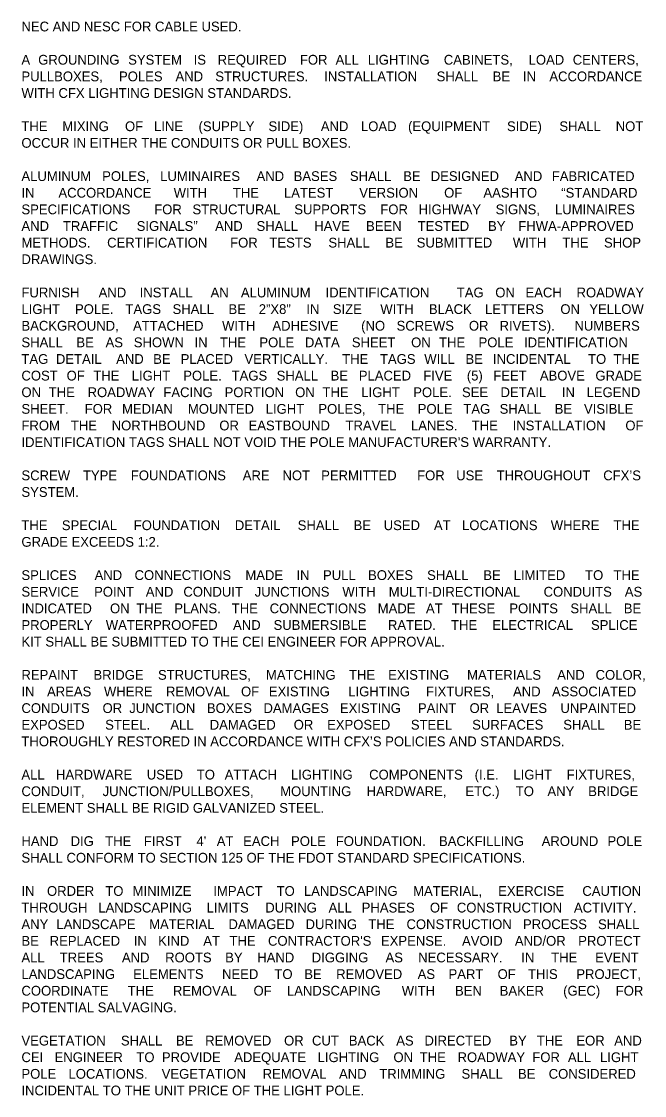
# Model space of a CAD drawing. Extents: x -55 to 2471539, y -90 to 3608906.
# Drawn here: x 568 to 1014, y 8 to 777 of the extents above; entities that cross this region are included whole.
import ezdxf

# ---------------------------------------------------------------- set-up
doc = ezdxf.new("R2010")
doc.units = 0
doc.layers.add('XSCell', color=7, linetype='Continuous')

msp = doc.modelspace()

# ---------------------------------------------------------------- texts
at = {"layer": 'XSCell'}
for s, p in [('NEC AND NESC FOR CABLE USED.', (568.01, 770.14)), ('GROUNDING ', (580.01, 746.34)), ('SYSTEM ', (644.47, 746.34)), ('IS ', (691.38, 746.34)), ('REQUIRED ', (708.58, 746.34)), ('FOR ', (767.49, 746.34)), ('LIGHTING ', (816.15, 746.34)), ('CABINETS, ', (870.55, 746.34)), ('LOAD ', (931.31, 746.34)), ('CENTERS, ', (962.92, 746.34)), ('A ', (568.01, 746.34)), ('ALL ', (793.05, 746.34)), ('PULLBOXES, ', (568.01, 734.44)), ('POLES ', (637.9, 734.44)), ('AND ', (678.37, 734.44)), ('STRUCTURES. ', (706.88, 734.44)), ('INSTALLATION ', (784.88, 734.44)), ('SHALL ', (865.42, 734.44)), ('BE ', (905.55, 734.44)), ('IN ', (927.24, 734.44)), ('ACCORDANCE ', (946.18, 734.44)), ('WITH CFX LIGHTING DESIGN STANDARDS.', (568.01, 722.54)), ('THE ', (568.01, 698.74)), ('MIXING ', (597.31, 698.74)), ('OF ', (642.19, 698.74)), ('LINE ', (663, 698.74)), ('(SUPPLY ', (694.88, 698.74)), ('SIDE) ', (744.95, 698.74)), ('AND ', (782.46, 698.74)), ('LOAD ', (811.22, 698.74)), ('(EQUIPMENT ', (844.96, 698.74)), ('SIDE) ', (915.82, 698.74)), ('SHALL ', (953.33, 698.74)), ('NOT ', (993.71, 698.74)), ('OCCUR IN EITHER THE CONDUITS OR PULL BOXES.', (568.01, 686.84)), ('ALUMINUM ', (568.01, 663.04)), ('POLES, ', (625.83, 663.04)), ('LUMINAIRES ', (667.41, 663.04)), ('AND ', (736.42, 663.04)), ('BASES ', (762.98, 663.04)), ('SHALL ', (803.29, 663.04)), ('BE ', (841.48, 663.04)), ('DESIGNED ', (861.21, 663.04)), ('AND ', (921.34, 663.04)), ('FABRICATED ', (947.9, 663.04)), ('IN ', (568.01, 651.14)), ('ACCORDANCE ', (594.51, 651.14)), ('WITH ', (677.06, 651.14)), ('THE ', (719.43, 651.14)), ('LATEST ', (756.05, 651.14)), ('VERSION ', (810.01, 651.14)), ('OF ', (870.8, 651.14)), ('AASHTO ', (898.93, 651.14)), ('“STANDARD ', (954.69, 651.14)), ('SPECIFICATIONS ', (568.01, 639.24)), ('FOR ', (663.12, 639.24)), ('STRUCTURAL ', (690.51, 639.24)), ('SUPPORTS ', (763.45, 639.24)), ('FOR ', (825.09, 639.24)), ('HIGHWAY ', (852.48, 639.24)), ('SIGNS, ', (907.69, 639.24)), ('LUMINAIRES ', (950.21, 639.24)), ('AND ', (568.01, 627.34)), ('TRAFFIC ', (597.7, 627.34)), ('SIGNALS” ', (650.56, 627.34)), ('AND ', (706.75, 627.34)), ('SHALL ', (736.44, 627.34)), ('HAVE ', (777.76, 627.34)), ('BEEN ', (814.87, 627.34)), ('TESTED ', (851.81, 627.34)), ('BY ', (902.26, 627.34)), ('FHWA-APPROVED ', (923.92, 627.34)), ('METHODS. ', (568.01, 615.44)), ('CERTIFICATION ', (629.39, 615.44)), ('FOR ', (717.5, 615.44)), ('TESTS ', (745.65, 615.44)), ('SHALL ', (787.89, 615.44)), ('BE ', (828.73, 615.44)), ('SUBMITTED ', (851.14, 615.44)), ('WITH ', (920.02, 615.44)), ('THE ', (955.54, 615.44)), ('SHOP ', (985.31, 615.44)), ('DRAWINGS.', (568.01, 603.54)), ('FURNISH ', (568.01, 579.74)), ('AND ', (623.29, 579.74)), ('INSTALL ', (652.69, 579.74)), ('AN ', (703.49, 579.74)), ('ALUMINUM ', (725.21, 579.74)), ('IDENTIFICATION ', (785.87, 579.74)), ('TAG ', (879.86, 579.74)), ('ON ', (907.43, 579.74)), ('EACH ', (929.1, 579.74)), ('ROADWAY ', (965.64, 579.74)), ('LIGHT ', (568.01, 567.84)), ('POLE. ', (606.39, 567.84)), ('TAGS ', (642.51, 567.84)), ('SHALL ', (676.24, 567.84)), ('BE ', (716.34, 567.84)), ('2”X8” ', (738.01, 567.84)), ('IN ', (772.11, 567.84)), ('SIZE ', (791.03, 567.84)), ('WITH ', (825.09, 567.84)), ('BLACK ', (859.87, 567.84)), ('LETTERS ', (900.07, 567.84)), ('ON ', (954.05, 567.84)), ('YELLOW ', (974.8, 567.84)), ('BACKGROUND, ', (568.01, 555.94)), ('ATTACHED ', (647.98, 555.94)), ('WITH ', (711.72, 555.94)), ('ADHESIVE ', (747.77, 555.94)), ('(NO ', (811.36, 555.94)), ('SCREWS ', (836.74, 555.94)), ('OR ', (888.54, 555.94)), ('RIVETS). ', (910.5, 555.94)), ('NUMBERS ', (964.15, 555.94)), ('SHALL ', (568.01, 544.04)), ('BE ', (607.37, 544.04)), ('AS ', (628.28, 544.04)), ('SHOWN ', (648.48, 544.04)), ('IN ', (691.99, 544.04)), ('THE ', (710.16, 544.04)), ('POLE ', (738.44, 544.04)), ('DATA ', (771.06, 544.04)), ('SHEET ', (804.66, 544.04)), ('ON ', (847.15, 544.04)), ('THE ', (867.16, 544.04)), ('POLE ', (895.44, 544.04)), ('IDENTIFICATION ', (928.06, 544.04)), ('TAG ', (568.01, 532.14)), ('DETAIL ', (592.69, 532.14)), ('AND ', (635.86, 532.14)), ('BE ', (662.38, 532.14)), ('PLACED ', (682.08, 532.14)), ('VERTICALLY. ', (727.77, 532.14)), ('THE ', (797.76, 532.14)), ('TAGS ', (824.83, 532.14)), ('WILL ', (856.59, 532.14)), ('BE ', (886.05, 532.14)), ('INCIDENTAL ', (905.75, 532.14)), ('TO ', (973.89, 532.14)), ('THE ', (992.12, 532.14)), ('COST ', (568.01, 520.24)), ('OF ', (600.37, 520.24)), ('THE ', (619.44, 520.24)), ('LIGHT ', (647, 520.24)), ('POLE. ', (683.91, 520.24)), ('TAGS ', (718.57, 520.24)), ('SHALL ', (750.83, 520.24)), ('BE ', (789.47, 520.24)), ('PLACED ', (809.66, 520.24)), ('FIVE ', (855.85, 520.24)), ('(5) ', (887.05, 520.24)), ('FEET ', (906.02, 520.24)), ('ABOVE ', (939.36, 520.24)), ('GRADE ', (979.17, 520.24)), ('ON ', (568.01, 508.34)), ('THE ', (587.57, 508.34)), ('ROADWAY ', (615.39, 508.34)), ('FACING ', (669.69, 508.34)), ('PORTION ', (713.51, 508.34)), ('ON ', (764.09, 508.34)), ('THE ', (783.65, 508.34)), ('LIGHT ', (811.48, 508.34)), ('POLE. ', (848.66, 508.34)), ('SEE ', (883.58, 508.34)), ('DETAIL ', (911.18, 508.34)), ('IN ', (955.12, 508.34)), ('LEGEND ', (972.84, 508.34)), ('SHEET. ', (568.01, 496.44)), ('FOR ', (613.33, 496.44)), ('MEDIAN ', (640.07, 496.44)), ('MOUNTED ', (687.27, 496.44)), ('LIGHT ', (742.99, 496.44)), ('POLES, ', (780.69, 496.44)), ('THE ', (823.52, 496.44)), ('POLE ', (851.88, 496.44)), ('TAG ', (884.57, 496.44)), ('SHALL ', (910.54, 496.44)), ('BE ', (949.98, 496.44)), ('VISIBLE ', (970.96, 496.44)), ('FROM ', (568.01, 484.54)), ('THE ', (603.39, 484.54)), ('NORTHBOUND ', (632.65, 484.54)), ('OR ', (709.75, 484.54)), ('EASTBOUND ', (730.69, 484.54)), ('TRAVEL ', (800.16, 484.54)), ('LANES. ', (847.03, 484.54)), ('THE ', (890.59, 484.54)), ('INSTALLATION ', (919.86, 484.54)), ('OF ', (1000.61, 484.54)), ("IDENTIFICATION TAGS SHALL NOT VOID THE POLE MANUFACTURER'S WARRANTY.", (568.01, 472.64)), ('SCREW ', (568.01, 448.84)), ('TYPE ', (612.05, 448.84)), ('FOUNDATIONS ', (646.38, 448.84)), ('ARE ', (726.54, 448.84)), ('NOT ', (755, 448.84)), ('PERMITTED ', (782.71, 448.84)), ('FOR ', (851.45, 448.84)), ('USE ', (879.44, 448.84)), ('THROUGHOUT ', (908.4, 448.84)), ('CFX’S ', (984.76, 448.84)), ('SYSTEM.', (568.01, 436.94)), ('THE ', (568.01, 413.14)), ('SPECIAL ', (596.95, 413.14)), ('FOUNDATION ', (648.45, 413.14)), ('DETAIL ', (720.86, 413.14)), ('SHALL ', (765.91, 413.14)), ('BE ', (805.93, 413.14)), ('USED ', (827.51, 413.14)), ('AT ', (863.48, 413.14)), ('LOCATIONS ', (883.63, 413.14)), ('WHERE ', (947.18, 413.14)), ('THE ', (992.12, 413.14)), ('GRADE EXCEEDS 1:2.', (568.01, 401.24)), ('SPLICES ', (568.01, 377.44)), ('AND ', (620.4, 377.44)), ('CONNECTIONS ', (649.03, 377.44)), ('MADE ', (728.42, 377.44)), ('IN ', (764.98, 377.44)), ('PULL ', (784.04, 377.44)), ('BOXES ', (816.31, 377.44)), ('SHALL ', (858.59, 377.44)), ('BE ', (898.84, 377.44)), ('LIMITED ', (920.65, 377.44)), ('TO ', (971.78, 377.44)), ('THE ', (992.12, 377.44)), ('SERVICE ', (568.01, 365.54)), ('POINT ', (620.07, 365.54)), ('AND ', (657.06, 365.54)), ('CONDUIT ', (684.01, 365.54)), ('JUNCTIONS ', (735.09, 365.54)), ('WITH ', (797.86, 365.54)), ('MULTI-DIRECTIONAL ', (831.11, 365.54)), ('CONDUITS ', (942.04, 365.54)), ('AS ', (1000.2, 365.54)), ('INDICATED ', (568.01, 353.64)), ('ON ', (631.45, 353.64)), ('THE ', (650.33, 353.64)), ('PLANS. ', (677.5, 353.64)), ('THE ', (718.68, 353.64)), ('CONNECTIONS ', (745.84, 353.64)), ('MADE ', (823.22, 353.64)), ('AT ', (857.76, 353.64)), ('THESE ', (876.13, 353.64)), ('POINTS ', (917.5, 353.64)), ('SHALL ', (961.24, 353.64)), ('BE ', (999.48, 353.64)), ('PROPERLY ', (568.01, 341.74)), ('WATERPROOFED ', (628.45, 341.74)), ('AND ', (719.6, 341.74)), ('SUBMERSIBLE ', (748.61, 341.74)), ('RATED. ', (830.55, 341.74)), ('THE ', (875.77, 341.74)), ('ELECTRICAL ', (905.32, 341.74)), ('SPLICE ', (975.98, 341.74)), ('KIT SHALL BE SUBMITTED TO THE CEI ENGINEER FOR APPROVAL.', (568.01, 329.84)), ('REPAINT ', (568.01, 306.04)), ('BRIDGE ', (619.62, 306.04)), ('STRUCTURES, ', (665.82, 306.04)), ('MATCHING ', (743.13, 306.04)), ('THE ', (802.64, 306.04)), ('EXISTING ', (830.7, 306.04)), ('MATERIALS ', (887.2, 306.04)), ('AND ', (951.78, 306.04)), ('COLOR, ', (979.3, 306.04)), ('IN ', (568.01, 294.14)), ('AREAS ', (586.33, 294.14)), ('WHERE ', (627.11, 294.14)), ('REMOVAL ', (671.54, 294.14)), ('OF ', (725.3, 294.14)), ('EXISTING ', (745.24, 294.14)), ('LIGHTING ', (802.12, 294.14)), ('FIXTURES, ', (857.79, 294.14)), ('AND ', (920.15, 294.14)), ('ASSOCIATED ', (948.05, 294.14)), ('CONDUITS ', (568.01, 282.24)), ('OR ', (626.11, 282.24)), ('JUNCTION ', (645.22, 282.24)), ('BOXES ', (700.86, 282.24)), ('DAMAGES ', (741.4, 282.24)), ('EXISTING ', (796.13, 282.24)), ('PAINT ', (852.01, 282.24)), ('OR ', (888.99, 282.24)), ('LEAVES ', (908.1, 282.24)), ('UNPAINTED ', (954.1, 282.24)), ('EXPOSED ', (568.01, 270.34)), ('STEEL. ', (627.98, 270.34)), ('ALL ', (674.69, 270.34)), ('DAMAGED ', (702.88, 270.34)), ('OR ', (763.04, 270.34)), ('EXPOSED ', (786.96, 270.34)), ('STEEL ', (846.94, 270.34)), ('SURFACES ', (890.89, 270.34)), ('SHALL ', (956.14, 270.34)), ('BE ', (999.48, 270.34)), ('THOROUGHLY RESTORED IN ACCORDANCE WITH CFX’S POLICIES AND STANDARDS. ', (568.01, 258.44)), ('ALL ', (568.01, 234.64)), ('HARDWARE ', (592.75, 234.64)), ('USED ', (657.8, 234.64)), ('TO ', (693.63, 234.64)), ('ATTACH ', (713.61, 234.64)), ('LIGHTING ', (761.04, 234.64)), ('COMPONENTS ', (817.08, 234.64)), ('(I.E. ', (892.66, 234.64)), ('LIGHT ', (920.42, 234.64)), ('FIXTURES, ', (958.58, 234.64)), ('CONDUIT, ', (568.01, 222.74)), ('JUNCTION/PULLBOXES, ', (626.15, 222.74)), ('MOUNTING ', (753.34, 222.74)), ('HARDWARE, ', (815.24, 222.74)), ('ETC.) ', (886.04, 222.74)), ('TO ', (922.13, 222.74)), ('ANY ', (944.79, 222.74)), ('BRIDGE ', (973.98, 222.74)), ('ELEMENT SHALL BE RIGID GALVANIZED STEEL.', (568.01, 210.84)), ('HAND ', (568.01, 187.04)), ('DIG ', (603.24, 187.04)), ('THE ', (627.99, 187.04)), ('FIRST ', (655.69, 187.04)), ("4' ", (693.4, 187.04)), ('AT ', (707.92, 187.04)), ('EACH ', (726.83, 187.04)), ('POLE ', (761.14, 187.04)), ('FOUNDATION. ', (793.18, 187.04)), ('BACKFILLING ', (867.11, 187.04)), ('AROUND ', (940.66, 187.04)), ('POLE ', (987.78, 187.04)), ('SHALL CONFORM TO SECTION 125 OF THE FDOT STANDARD SPECIFICATIONS.', (568.01, 175.14)), ('IN ', (568.01, 151.34)), ('ORDER ', (586.31, 151.34)), ('TO ', (628.08, 151.34)), ('MINIMIZE ', (647.66, 151.34)), ('IMPACT ', (705.48, 151.34)), ('TO ', (750.79, 151.34)), ('LANDSCAPING ', (770.36, 151.34)), ('MATERIAL, ', (848.58, 151.34)), ('EXERCISE ', (909.49, 151.34)), ('CAUTION ', (969.8, 151.34)), ('THROUGH ', (568.01, 139.44)), ('LANDSCAPING ', (623.09, 139.44)), ('LIMITS ', (700.68, 139.44)), ('DURING ', (742.68, 139.44)), ('ALL ', (788.03, 139.44)), ('PHASES ', (811.75, 139.44)), ('OF ', (860.6, 139.44)), ('CONSTRUCTION ', (879.89, 139.44)), ('ACTIVITY. ', (963.78, 139.44)), ('ANY ', (568.01, 127.54)), ('LANDSCAPE ', (593.07, 127.54)), ('MATERIAL ', (659.49, 127.54)), ('DAMAGED ', (716.29, 127.54)), ('DURING ', (771.54, 127.54)), ('THE ', (816.47, 127.54)), ('CONSTRUCTION ', (843.83, 127.54)), ('PROCESS ', (927.29, 127.54)), ('SHALL ', (981.03, 127.54)), ('BE ', (568.01, 115.64)), ('REPLACED ', (588.23, 115.64)), ('IN ', (648.46, 115.64)), ('KIND ', (665.93, 115.64)), ('AT ', (698.24, 115.64)), ('THE ', (717.04, 115.64)), ("CONTRACTOR'S ", (744.63, 115.64)), ('EXPENSE. ', (825.54, 115.64)), ('AVOID ', (883.61, 115.64)), ('AND/OR ', (921.45, 115.64)), ('PROTECT ', (966.83, 115.64)), ('ALL ', (568.01, 103.74)), ('TREES ', (595.45, 103.74)), ('AND ', (639.99, 103.74)), ('ROOTS ', (670.96, 103.74)), ('BY ', (713.96, 103.74)), ('HAND ', (736.91, 103.74)), ('DIGGING ', (775.95, 103.74)), ('AS ', (828.8, 103.74)), ('NECESSARY. ', (852.22, 103.74)), ('IN ', (926.06, 103.74)), ('THE ', (947.46, 103.74)), ('EVENT ', (978.98, 103.74)), ('LANDSCAPING ', (568.01, 91.84)), ('ELEMENTS ', (648.02, 91.84)), ('NEED ', (711.71, 91.84)), ('TO ', (749.23, 91.84)), ('BE ', (770.6, 91.84)), ('REMOVED ', (793.44, 91.84)), ('AS ', (851.82, 91.84)), ('PART ', (873.94, 91.84)), ('OF ', (909.09, 91.84)), ('THIS ', (930.81, 91.84)), ('PROJECT, ', (965.48, 91.84)), ('COORDINATE ', (568.01, 79.94)), ('THE ', (644.1, 79.94)), ('REMOVAL ', (676.52, 79.94)), ('OF ', (734.26, 79.94)), ('LANDSCAPING ', (758.19, 79.94)), ('WITH ', (840.42, 79.94)), ('BEN ', (878.59, 79.94)), ('BAKER ', (910.58, 79.94)), ('(GEC) ', (956.07, 79.94)), ('FOR ', (993.73, 79.94)), ('POTENTIAL SALVAGING.', (568.01, 68.04)), ('VEGETATION ', (568.01, 44.24)), ('SHALL ', (639.27, 44.24)), ('BE ', (678.67, 44.24)), ('REMOVED ', (699.63, 44.24)), ('OR ', (756.14, 44.24)), ('CUT ', (776.13, 44.24)), ('BACK ', (802.52, 44.24)), ('AS ', (836.47, 44.24)), ('DIRECTED ', (856.71, 44.24)), ('BY ', (917.44, 44.24)), ('THE ', (937.2, 44.24)), ('EOR ', (965.52, 44.24)), ('AND ', (992.65, 44.24)), ('CEI ', (568.01, 32.34)), ('ENGINEER ', (591.75, 32.34)), ('TO ', (650.35, 32.34)), ('PROVIDE ', (668.61, 32.34)), ('ADEQUATE ', (720.42, 32.34)), ('LIGHTING ', (780.17, 32.34)), ('ON ', (834.49, 32.34)), ('THE ', (853.31, 32.34)), ('ROADWAY ', (880.4, 32.34)), ('FOR ', (933.96, 32.34)), ('ALL ', (959.44, 32.34)), ('LIGHT ', (982.46, 32.34)), ('POLE ', (568.01, 20.44)), ('LOCATIONS. ', (601.72, 20.44)), ('VEGETATION ', (668.47, 20.44)), ('REMOVAL ', (740.78, 20.44)), ('AND ', (795.48, 20.44)), ('TRIMMING ', (824.32, 20.44)), ('SHALL ', (883.22, 20.44)), ('BE ', (923.68, 20.44)), ('CONSIDERED ', (945.69, 20.44)), ('INCIDENTAL TO THE UNIT PRICE OF THE LIGHT POLE.', (568.01, 8.54))]:
    msp.add_text(s, height=7, dxfattribs=at).set_placement(p)

doc.saveas('drawing.dxf')
